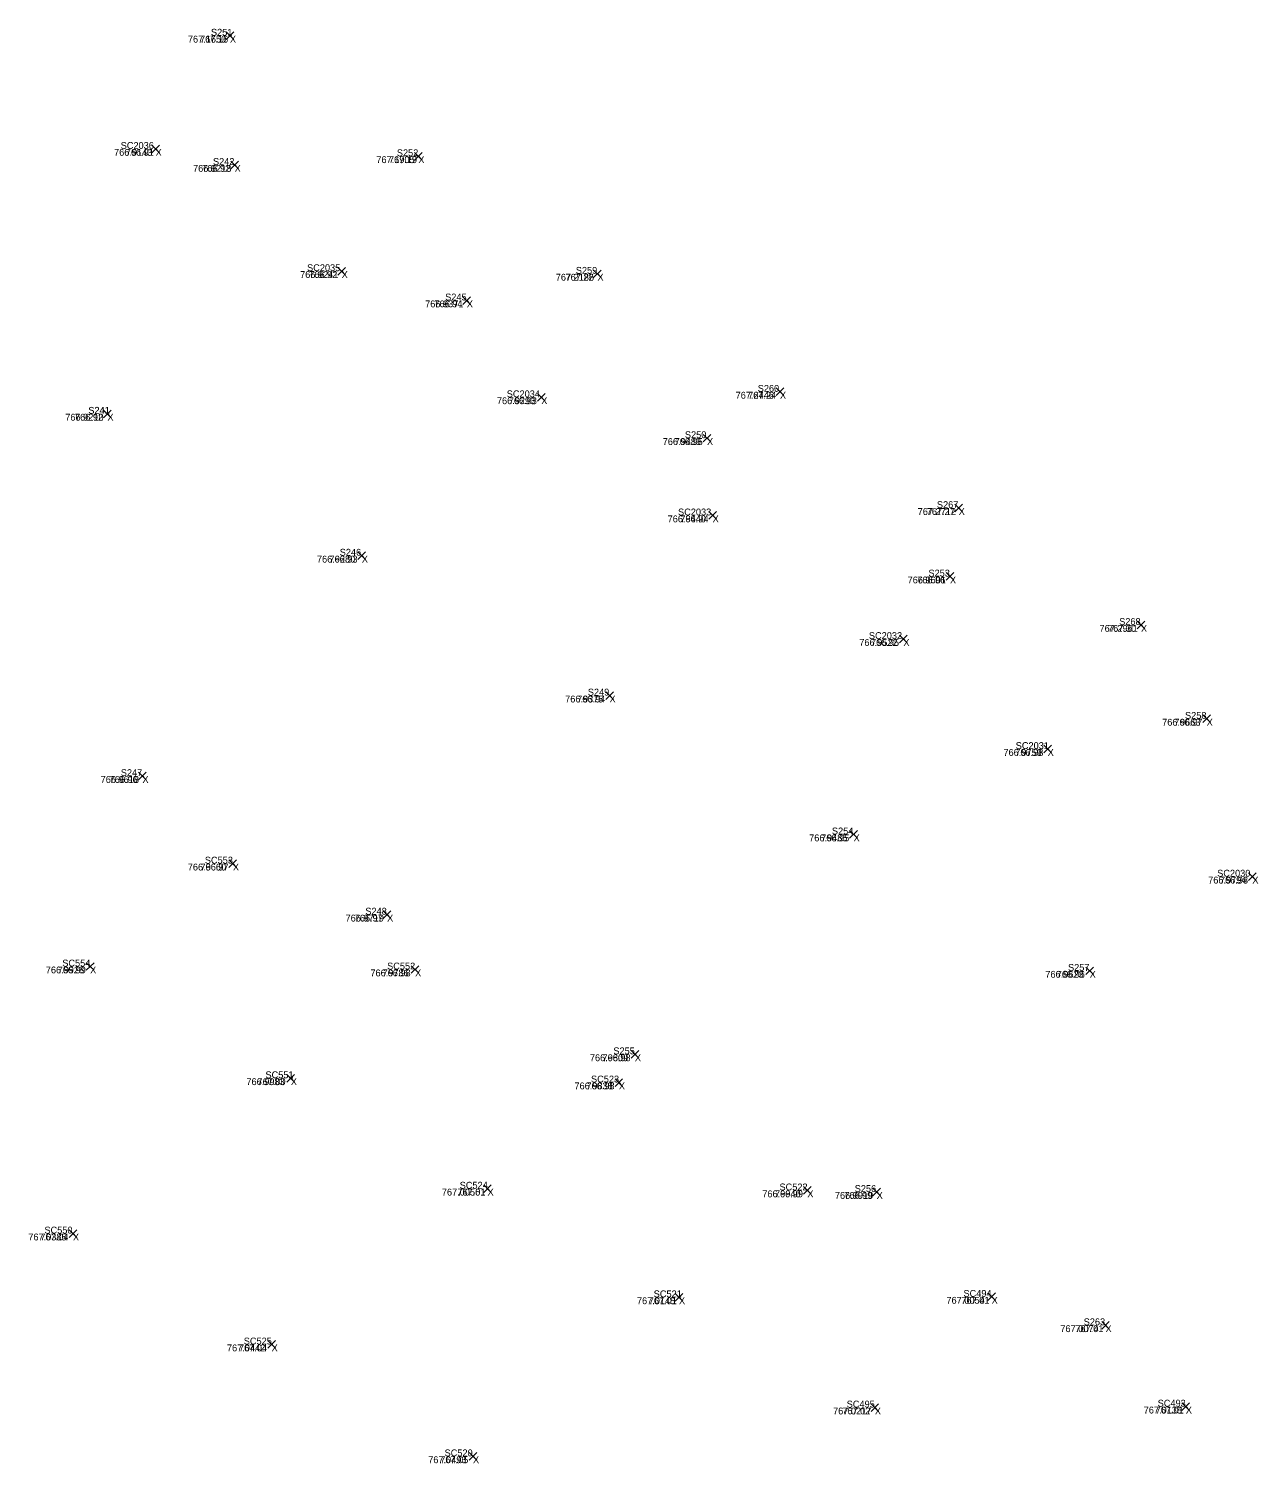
# Model space of a CAD drawing. Extents: x 1845019 to 1877956, y 680444 to 701081.
# Drawn here: x 1857636.8 to 1857647.54, y 694303.26 to 694315.8 of the extents above; entities that cross this region are included whole.
import ezdxf

# ---------------------------------------------------------------- set-up
doc = ezdxf.new("R2010")
doc.units = 0
for name, color, linetype in [('SV_X_Random_Point', 7, 'Continuous'), ('SV_X_Text_Comment', 7, 'Continuous'), ('SV_X_Text_Elevation', 7, 'Continuous'), ('SV_X_Text_Name', 7, 'Continuous')]:
    doc.layers.add(name, color=color, linetype=linetype)

msp = doc.modelspace()

# ---------------------------------------------------------------- linework, layer by layer
at = {"layer": 'SV_X_Random_Point'}
for p, q in [((1857638.525, 694315.704), (1857638.592, 694315.771)), ((1857638.525, 694315.771), (1857638.592, 694315.704)), ((1857638.525, 694315.704), (1857638.592, 694315.771)), ((1857638.525, 694315.771), (1857638.592, 694315.704)), ((1857637.877, 694314.715), (1857637.944, 694314.781)), ((1857637.877, 694314.781), (1857637.944, 694314.715)), ((1857637.877, 694314.715), (1857637.944, 694314.781)), ((1857637.877, 694314.781), (1857637.944, 694314.715)), ((1857640.172, 694314.651), (1857640.238, 694314.717)), ((1857640.172, 694314.717), (1857640.238, 694314.651)), ((1857640.172, 694314.651), (1857640.238, 694314.717)), ((1857640.172, 694314.717), (1857640.238, 694314.651)), ((1857638.566, 694314.575), (1857638.633, 694314.641)), ((1857638.566, 694314.641), (1857638.633, 694314.575)), ((1857638.566, 694314.575), (1857638.633, 694314.641)), ((1857638.566, 694314.641), (1857638.633, 694314.575)), ((1857639.502, 694313.646), (1857639.568, 694313.713)), ((1857639.502, 694313.713), (1857639.568, 694313.646)), ((1857639.502, 694313.646), (1857639.568, 694313.713)), ((1857639.502, 694313.713), (1857639.568, 694313.646)), ((1857641.735, 694313.624), (1857641.802, 694313.69)), ((1857641.735, 694313.69), (1857641.802, 694313.624)), ((1857641.735, 694313.624), (1857641.802, 694313.69)), ((1857641.735, 694313.69), (1857641.802, 694313.624)), ((1857640.594, 694313.39), (1857640.661, 694313.457)), ((1857640.594, 694313.457), (1857640.661, 694313.39)), ((1857640.594, 694313.39), (1857640.661, 694313.457)), ((1857640.594, 694313.457), (1857640.661, 694313.39)), ((1857641.245, 694312.545), (1857641.312, 694312.612)), ((1857641.245, 694312.612), (1857641.312, 694312.545)), ((1857641.245, 694312.545), (1857641.312, 694312.612)), ((1857641.245, 694312.612), (1857641.312, 694312.545)), ((1857643.33, 694312.593), (1857643.397, 694312.66)), ((1857643.33, 694312.66), (1857643.397, 694312.593)), ((1857643.33, 694312.593), (1857643.397, 694312.66)), ((1857643.33, 694312.66), (1857643.397, 694312.593)), ((1857637.455, 694312.4), (1857637.522, 694312.467)), ((1857637.455, 694312.467), (1857637.522, 694312.4)), ((1857637.455, 694312.4), (1857637.522, 694312.467)), ((1857637.455, 694312.467), (1857637.522, 694312.4)), ((1857642.693, 694312.188), (1857642.76, 694312.254)), ((1857642.693, 694312.254), (1857642.76, 694312.188)), ((1857642.693, 694312.188), (1857642.76, 694312.254)), ((1857642.693, 694312.254), (1857642.76, 694312.188)), ((1857642.742, 694311.512), (1857642.808, 694311.579)), ((1857642.742, 694311.579), (1857642.808, 694311.512)), ((1857642.742, 694311.512), (1857642.808, 694311.579)), ((1857642.742, 694311.579), (1857642.808, 694311.512)), ((1857644.891, 694311.576), (1857644.957, 694311.643)), ((1857644.891, 694311.643), (1857644.957, 694311.576)), ((1857644.891, 694311.576), (1857644.957, 694311.643)), ((1857644.891, 694311.643), (1857644.957, 694311.576)), ((1857639.677, 694311.161), (1857639.744, 694311.228)), ((1857639.677, 694311.228), (1857639.744, 694311.161)), ((1857639.677, 694311.161), (1857639.744, 694311.228)), ((1857639.677, 694311.228), (1857639.744, 694311.161)), ((1857644.815, 694310.979), (1857644.882, 694311.046)), ((1857644.815, 694311.046), (1857644.882, 694310.979)), ((1857644.815, 694310.979), (1857644.882, 694311.046)), ((1857644.815, 694311.046), (1857644.882, 694310.979)), ((1857646.482, 694310.556), (1857646.549, 694310.622)), ((1857646.482, 694310.622), (1857646.549, 694310.556)), ((1857646.482, 694310.556), (1857646.549, 694310.622)), ((1857646.482, 694310.622), (1857646.549, 694310.556)), ((1857644.408, 694310.432), (1857644.475, 694310.499)), ((1857644.408, 694310.499), (1857644.475, 694310.432)), ((1857644.408, 694310.432), (1857644.475, 694310.499)), ((1857644.408, 694310.499), (1857644.475, 694310.432)), ((1857641.841, 694309.938), (1857641.908, 694310.005)), ((1857641.841, 694310.005), (1857641.908, 694309.938)), ((1857641.841, 694309.938), (1857641.908, 694310.005)), ((1857641.841, 694310.005), (1857641.908, 694309.938)), ((1857647.057, 694309.736), (1857647.123, 694309.803)), ((1857647.057, 694309.803), (1857647.123, 694309.736)), ((1857647.057, 694309.736), (1857647.123, 694309.803)), ((1857647.057, 694309.803), (1857647.123, 694309.736)), ((1857645.668, 694309.471), (1857645.735, 694309.538)), ((1857645.668, 694309.538), (1857645.735, 694309.471)), ((1857645.668, 694309.471), (1857645.735, 694309.538)), ((1857645.668, 694309.538), (1857645.735, 694309.471)), ((1857637.762, 694309.235), (1857637.828, 694309.302)), ((1857637.762, 694309.302), (1857637.828, 694309.235)), ((1857637.762, 694309.235), (1857637.828, 694309.302)), ((1857637.762, 694309.302), (1857637.828, 694309.235)), ((1857643.972, 694308.725), (1857644.039, 694308.792)), ((1857643.972, 694308.792), (1857644.039, 694308.725)), ((1857643.972, 694308.725), (1857644.039, 694308.792)), ((1857643.972, 694308.792), (1857644.039, 694308.725)), ((1857638.551, 694308.471), (1857638.618, 694308.537)), ((1857638.551, 694308.537), (1857638.618, 694308.471)), ((1857638.551, 694308.471), (1857638.618, 694308.537)), ((1857638.551, 694308.537), (1857638.618, 694308.471)), ((1857647.456, 694308.356), (1857647.523, 694308.423)), ((1857647.456, 694308.423), (1857647.523, 694308.356)), ((1857647.456, 694308.356), (1857647.523, 694308.423)), ((1857647.456, 694308.423), (1857647.523, 694308.356)), ((1857639.898, 694308.025), (1857639.965, 694308.091)), ((1857639.898, 694308.091), (1857639.965, 694308.025)), ((1857639.898, 694308.025), (1857639.965, 694308.091)), ((1857639.898, 694308.091), (1857639.965, 694308.025)), ((1857637.305, 694307.572), (1857637.372, 694307.638)), ((1857637.305, 694307.638), (1857637.372, 694307.572)), ((1857637.305, 694307.572), (1857637.372, 694307.638)), ((1857637.305, 694307.638), (1857637.372, 694307.572)), ((1857640.142, 694307.546), (1857640.209, 694307.612)), ((1857640.142, 694307.612), (1857640.209, 694307.546)), ((1857640.142, 694307.546), (1857640.209, 694307.612)), ((1857640.142, 694307.612), (1857640.209, 694307.546)), ((1857646.034, 694307.534), (1857646.101, 694307.6)), ((1857646.034, 694307.6), (1857646.101, 694307.534)), ((1857646.034, 694307.534), (1857646.101, 694307.6)), ((1857646.034, 694307.6), (1857646.101, 694307.534)), ((1857642.063, 694306.804), (1857642.13, 694306.871)), ((1857642.063, 694306.871), (1857642.13, 694306.804)), ((1857642.063, 694306.804), (1857642.13, 694306.871)), ((1857642.063, 694306.871), (1857642.13, 694306.804)), ((1857639.057, 694306.595), (1857639.124, 694306.662)), ((1857639.057, 694306.662), (1857639.124, 694306.595)), ((1857639.057, 694306.595), (1857639.124, 694306.662)), ((1857639.057, 694306.662), (1857639.124, 694306.595)), ((1857641.923, 694306.558), (1857641.989, 694306.625)), ((1857641.923, 694306.625), (1857641.989, 694306.558)), ((1857641.923, 694306.558), (1857641.989, 694306.625)), ((1857641.923, 694306.625), (1857641.989, 694306.558)), ((1857640.776, 694305.63), (1857640.842, 694305.697)), ((1857640.776, 694305.697), (1857640.842, 694305.63)), ((1857640.776, 694305.63), (1857640.842, 694305.697)), ((1857640.776, 694305.697), (1857640.842, 694305.63)), ((1857643.569, 694305.616), (1857643.636, 694305.683)), ((1857643.569, 694305.683), (1857643.636, 694305.616)), ((1857643.569, 694305.616), (1857643.636, 694305.683)), ((1857643.569, 694305.683), (1857643.636, 694305.616)), ((1857644.175, 694305.601), (1857644.241, 694305.668)), ((1857644.175, 694305.668), (1857644.241, 694305.601)), ((1857644.175, 694305.601), (1857644.241, 694305.668)), ((1857644.175, 694305.668), (1857644.241, 694305.601)), ((1857637.155, 694305.238), (1857637.222, 694305.305)), ((1857637.155, 694305.305), (1857637.222, 694305.238)), ((1857637.155, 694305.238), (1857637.222, 694305.305)), ((1857637.155, 694305.305), (1857637.222, 694305.238)), ((1857642.447, 694304.681), (1857642.514, 694304.748)), ((1857642.447, 694304.748), (1857642.514, 694304.681)), ((1857642.447, 694304.681), (1857642.514, 694304.748)), ((1857642.447, 694304.748), (1857642.514, 694304.681)), ((1857645.178, 694304.686), (1857645.245, 694304.753)), ((1857645.178, 694304.753), (1857645.245, 694304.686)), ((1857645.178, 694304.686), (1857645.245, 694304.753)), ((1857645.178, 694304.753), (1857645.245, 694304.686)), ((1857646.173, 694304.437), (1857646.239, 694304.504)), ((1857646.173, 694304.504), (1857646.239, 694304.437)), ((1857646.173, 694304.437), (1857646.239, 694304.504)), ((1857646.173, 694304.504), (1857646.239, 694304.437)), ((1857638.89, 694304.27), (1857638.956, 694304.337)), ((1857638.89, 694304.337), (1857638.956, 694304.27)), ((1857638.89, 694304.27), (1857638.956, 694304.337)), ((1857638.89, 694304.337), (1857638.956, 694304.27)), ((1857644.159, 694303.718), (1857644.225, 694303.785)), ((1857644.159, 694303.785), (1857644.225, 694303.718)), ((1857644.159, 694303.718), (1857644.225, 694303.785)), ((1857644.159, 694303.785), (1857644.225, 694303.718)), ((1857646.874, 694303.727), (1857646.941, 694303.794)), ((1857646.874, 694303.794), (1857646.941, 694303.727)), ((1857646.874, 694303.727), (1857646.941, 694303.794)), ((1857646.874, 694303.794), (1857646.941, 694303.727)), ((1857640.649, 694303.292), (1857640.715, 694303.359)), ((1857640.649, 694303.359), (1857640.715, 694303.292)), ((1857640.649, 694303.292), (1857640.715, 694303.359)), ((1857640.649, 694303.359), (1857640.715, 694303.292))]:
    msp.add_line(p, q, dxfattribs=at)

# ---------------------------------------------------------------- texts
at = {"layer": 'SV_X_Text_Comment'}
for p in [(1857638.559, 694315.677), (1857637.91, 694314.688), (1857640.205, 694314.624), (1857638.6, 694314.548), (1857639.535, 694313.62), (1857641.769, 694313.597), (1857640.628, 694313.364), (1857641.278, 694312.518), (1857643.363, 694312.566), (1857637.489, 694312.374), (1857642.726, 694312.161), (1857642.775, 694311.486), (1857644.924, 694311.55), (1857639.711, 694311.134), (1857644.848, 694310.952), (1857646.516, 694310.529), (1857644.441, 694310.406), (1857641.874, 694309.912), (1857647.09, 694309.709), (1857645.701, 694309.445), (1857637.795, 694309.209), (1857644.006, 694308.699), (1857638.585, 694308.444), (1857647.489, 694308.33), (1857639.932, 694307.998), (1857637.338, 694307.545), (1857640.176, 694307.519), (1857646.068, 694307.507), (1857642.096, 694306.778), (1857639.091, 694306.569), (1857641.956, 694306.532), (1857640.809, 694305.604), (1857643.602, 694305.589), (1857644.208, 694305.575), (1857637.188, 694305.212), (1857642.481, 694304.655), (1857645.212, 694304.659), (1857646.206, 694304.411), (1857638.923, 694304.243), (1857644.192, 694303.692), (1857646.908, 694303.7), (1857640.682, 694303.266)]:
    msp.add_text('X', height=0.06, dxfattribs=at).set_placement(p)
at = {"layer": 'SV_X_Text_Elevation'}
for s, p in [('767.1650', (1857638.192, 694315.677)), ('767.16', (1857638.298, 694315.677)), ('766.9143', (1857637.547, 694314.688)), ('766.91', (1857637.65, 694314.688)), ('767.1905', (1857639.838, 694314.624)), ('767.19', (1857639.948, 694314.624)), ('766.9218', (1857638.237, 694314.548)), ('766.92', (1857638.317, 694314.548)), ('766.9241', (1857639.172, 694313.62)), ('766.92', (1857639.252, 694313.62)), ('767.2186', (1857641.405, 694313.597)), ('767.22', (1857641.49, 694313.597)), ('766.9371', (1857640.264, 694313.364)), ('766.94', (1857640.345, 694313.364)), ('766.9293', (1857640.891, 694312.518)), ('766.93', (1857640.995, 694312.518)), ('767.2446', (1857642.976, 694312.566)), ('767.24', (1857643.085, 694312.566)), ('766.9210', (1857637.121, 694312.374)), ('766.92', (1857637.206, 694312.374)), ('766.9489', (1857642.339, 694312.161)), ('766.95', (1857642.443, 694312.161)), ('766.9440', (1857642.382, 694311.486)), ('766.94', (1857642.493, 694311.486)), ('767.2712', (1857644.566, 694311.55)), ('767.27', (1857644.645, 694311.55)), ('766.9280', (1857639.319, 694311.134)), ('766.93', (1857639.428, 694311.134)), ('766.9601', (1857644.478, 694310.952)), ('766.96', (1857644.562, 694310.952)), ('767.2961', (1857646.154, 694310.529)), ('767.30', (1857646.229, 694310.529)), ('766.9522', (1857644.056, 694310.406)), ('766.95', (1857644.158, 694310.406)), ('766.9375', (1857641.487, 694309.912)), ('766.94', (1857641.592, 694309.912)), ('766.9663', (1857646.701, 694309.709)), ('766.97', (1857646.807, 694309.709)), ('766.9759', (1857645.315, 694309.445)), ('766.98', (1857645.418, 694309.445)), ('766.9618', (1857637.43, 694309.209)), ('766.96', (1857637.508, 694309.209)), ('766.9485', (1857643.618, 694308.699)), ('766.95', (1857643.723, 694308.699)), ('766.9660', (1857638.191, 694308.444)), ('766.97', (1857638.302, 694308.444)), ('766.9794', (1857647.103, 694308.33)), ('766.98', (1857647.206, 694308.33)), ('766.9719', (1857639.569, 694307.998)), ('766.97', (1857639.649, 694307.998)), ('766.9928', (1857636.951, 694307.545)), ('766.99', (1857637.055, 694307.545)), ('766.9786', (1857639.786, 694307.519)), ('766.98', (1857639.892, 694307.519)), ('766.9623', (1857645.681, 694307.507)), ('766.96', (1857645.781, 694307.507)), ('766.9809', (1857641.703, 694306.778)), ('766.98', (1857641.813, 694306.778)), ('766.9983', (1857638.703, 694306.569)), ('767.00', (1857638.8, 694306.569)), ('766.9838', (1857641.568, 694306.532)), ('766.98', (1857641.673, 694306.532)), ('767.0056', (1857640.41, 694305.604)), ('767.01', (1857640.546, 694305.604)), ('766.9940', (1857643.209, 694305.589)), ('766.99', (1857643.319, 694305.589)), ('766.9919', (1857643.843, 694305.575)), ('766.99', (1857643.925, 694305.575)), ('767.0385', (1857636.798, 694305.212)), ('767.04', (1857636.903, 694305.212)), ('767.0145', (1857642.114, 694304.655)), ('767.01', (1857642.217, 694304.655)), ('767.0054', (1857644.817, 694304.659)), ('767.01', (1857644.948, 694304.659)), ('767.0074', (1857645.812, 694304.411)), ('767.01', (1857645.943, 694304.411)), ('767.0442', (1857638.533, 694304.243)), ('767.04', (1857638.638, 694304.243)), ('767.0217', (1857643.827, 694303.692)), ('767.02', (1857643.907, 694303.692)), ('767.0138', (1857646.54, 694303.7)), ('767.01', (1857646.644, 694303.7)), ('767.0493', (1857640.291, 694303.266)), ('767.05', (1857640.396, 694303.266))]:
    msp.add_text(s, height=0.06, dxfattribs=at).set_placement(p)
at = {"layer": 'SV_X_Text_Name'}
for s, p in [('S251', (1857638.393, 694315.737)), ('S251', (1857638.394, 694315.737)), ('SC2036', (1857637.605, 694314.748)), ('SC2036', (1857637.605, 694314.748)), ('S252', (1857640.017, 694314.684)), ('S252', (1857640.017, 694314.684)), ('S242', (1857638.411, 694314.608)), ('S242', (1857638.411, 694314.608)), ('SC2035', (1857639.233, 694313.68)), ('SC2035', (1857639.233, 694313.68)), ('S259', (1857641.58, 694313.657)), ('S259', (1857641.58, 694313.657)), ('S245', (1857640.439, 694313.424)), ('S245', (1857640.439, 694313.424)), ('S260', (1857643.169, 694312.626)), ('S260', (1857643.169, 694312.626)), ('SC2034', (1857640.977, 694312.578)), ('SC2034', (1857640.977, 694312.578)), ('S241', (1857637.322, 694312.434)), ('S241', (1857637.323, 694312.434)), ('S250', (1857642.533, 694312.221)), ('S250', (1857642.533, 694312.221)), ('S267', (1857644.734, 694311.61)), ('S267', (1857644.734, 694311.61)), ('SC2033', (1857642.473, 694311.546)), ('SC2033', (1857642.473, 694311.546)), ('S246', (1857639.518, 694311.194)), ('S246', (1857639.518, 694311.194)), ('S253', (1857644.66, 694311.012)), ('S253', (1857644.66, 694311.012)), ('S268', (1857646.326, 694310.589)), ('S268', (1857646.326, 694310.589)), ('SC2032', (1857644.14, 694310.466)), ('SC2032', (1857644.14, 694310.466)), ('S249', (1857641.685, 694309.972)), ('S249', (1857641.685, 694309.972)), ('S258', (1857646.901, 694309.769)), ('S258', (1857646.901, 694309.769)), ('SC2031', (1857645.422, 694309.505)), ('SC2031', (1857645.423, 694309.505)), ('S247', (1857637.606, 694309.269)), ('S247', (1857637.606, 694309.269)), ('S254', (1857643.817, 694308.759)), ('S254', (1857643.817, 694308.759)), ('SC553', (1857638.34, 694308.504)), ('SC553', (1857638.34, 694308.504)), ('SC2030', (1857647.182, 694308.39)), ('SC2030', (1857647.182, 694308.39)), ('S248', (1857639.742, 694308.058)), ('S248', (1857639.742, 694308.058)), ('SC554', (1857637.095, 694307.605)), ('SC554', (1857637.095, 694307.605)), ('SC552', (1857639.932, 694307.579)), ('SC552', (1857639.932, 694307.579)), ('S257', (1857645.879, 694307.567)), ('S257', (1857645.879, 694307.567)), ('S255', (1857641.908, 694306.838)), ('S255', (1857641.908, 694306.838)), ('SC551', (1857638.87, 694306.629)), ('SC551', (1857638.869, 694306.629)), ('SC523', (1857641.713, 694306.592)), ('SC523', (1857641.713, 694306.592)), ('SC524', (1857640.566, 694305.664)), ('SC524', (1857640.566, 694305.664)), ('SC522', (1857643.359, 694305.649)), ('SC522', (1857643.359, 694305.649)), ('S256', (1857644.016, 694305.635)), ('S256', (1857644.016, 694305.635)), ('SC550', (1857636.939, 694305.272)), ('SC550', (1857636.939, 694305.272)), ('SC521', (1857642.26, 694304.715)), ('SC521', (1857642.261, 694304.715)), ('SC494', (1857644.966, 694304.719)), ('SC494', (1857644.966, 694304.719)), ('S263', (1857646.016, 694304.471)), ('S263', (1857646.016, 694304.471)), ('SC525', (1857638.68, 694304.303)), ('SC525', (1857638.68, 694304.303)), ('SC495', (1857643.946, 694303.752)), ('SC495', (1857643.946, 694303.752)), ('SC493', (1857646.662, 694303.76)), ('SC493', (1857646.662, 694303.76)), ('SC520', (1857640.434, 694303.326)), ('SC520', (1857640.434, 694303.326))]:
    msp.add_text(s, height=0.06, dxfattribs=at).set_placement(p)

doc.saveas('drawing.dxf')
